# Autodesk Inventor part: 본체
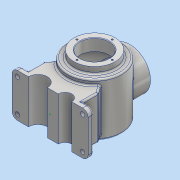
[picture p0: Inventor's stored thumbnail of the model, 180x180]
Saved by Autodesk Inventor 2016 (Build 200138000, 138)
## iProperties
Created: 2018-08
Part Number: 본체
Material: 알루미늄 6061
Document SubType Name: Modeling
Designer: 605-08
Density: 2.7 g/cm^3
Appearance: 알루미늄 - 평지
Mass: 1878.27 g
Surface Area: 1089.41 cm^2
Volume: 695.654 cm^3
Author: 605-08
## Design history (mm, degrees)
sketch "스케치1"
  geometry: 1 further point
sketch "스케치2"
  geometry: L1 (-70, 40)-(70, 40); L2 (70, 40)-(70, -40); L3 (70, -40)-(-70, -40); L4 (-70, -40)-(-70, 40); L5 (-70, 40)-(70, -40); L6 (70, 40)-(-70, -40); 1 further point
  constraints: 12 end point, 2 midpoint, 2 parallel, 1 horizontal, 1 perpendicular
  dimensions: "d0" = 140 distance of L2.end L3.end; "d1" = 80 distance of L1.end L2.end
extrude "돌출1" new body sketch "스케치2" distance "d2" = 10; taper "d3" = 0 deg
sketch "스케치5"
  geometry: L1 (-70, 0)-(-70, 10) reference; L2 (-50, 38.563)-(0, 109.97); L3 (-70, 10)-(70, 10) reference; L4 (-50, 10)-(50, 10); L5 (70, 0)-(-70, 0) reference; L6 (-50, 10)-(-50, 38.563); L7 (0, 10)-(0, 109.97); L8 (50, 10)-(50, 38.563); L9 (50, 38.563)-(0, 109.97); 3 further points
  constraints: 12 end point, 3 midpoint, 1 coincident, 1 horizontal, 1 perpendicular, 1 symmetric about line, 1 vertical, 1 vertical alignment
  dimensions: "d11" = 55 deg angle of L3 L2; "d12" = 100 distance of L4.start L4.end; "d13" = 99.97036 distance of point (0, 10) L2.end
extrude "돌출2" join sketch "스케치5" stored distance "d14" = 80; taper "d15" = 0 deg
sketch "스케치7"
  geometry: 1 further point
sketch "스케치8"
  geometry: C1 r 50 at (0, 82); 1 further point
  constraints: 1 centre point, 1 vertical alignment
  dimensions: "d24" = 100 diameter of C1; "d25" = 82 distance of C1.centre point (0, 0)
extrude "돌출3" join sketch "스케치8" distance "d26" = 50; taper "d28" = 0 deg; dims "d27" = 58, "d29" = 0
sketch "스케치9"
  geometry: L1 (32, -58)-(132, -58) reference; L2 (82, 58)-(82, -58); L3 (132, -58)-(132, 50) reference; L4 (32, -58)-(32, 50) reference; L5 (132, -46.671)-(132, -58); L6 (132, -58)-(82, -58); A1 r 116 centre (82, 58) between (82, -58) and (132, -46.671); 1 further point
  constraints: 6 end point, 2 collinear, 2 point on circle, 1 centre point, 1 midpoint, 1 point on line, 1 vertical, 1 vertical alignment
  dimensions: "d30" = 116 radius of A1
revolve "회전1" sketch "스케치9" stored, may be unused: angle "d34" = 90 deg
sketch "스케치10"
  geometry: C1 r 38 at (0, 0); 1 further point
  constraints: 1 centre point, 1 vertical alignment
  dimensions: "d35" = 76 diameter of C1; "d36" = 82 distance of point (0, -82) C1.centre
extrude "돌출4" join sketch "스케치10" distance "d37" = 12; taper "d38" = 0 deg
node "작업 평면1"
sketch "스케치11"
  geometry: L1 (50, 50)-(-50, 50) reference; C1 r 38 at (0, 0); 1 further point
  constraints: 1 centre point, 1 coincident
  dimensions: "d40" = 76 diameter of C1; "d41" = 50 distance from line of L1 C1.centre
extrude "돌출5" join sketch "스케치11" stored distance "d42" = 12; taper "d43" = 0 deg
sketch "스케치12"
  geometry: 2 further points
  constraints: 1 vertical alignment
  dimensions: "d44" = 82 distance of point (0, -82) point (0, 0)
hole "구멍1" sketch "스케치12" at (0, 0) diameter "d45" = 54; stored, may be unused: countersink angle "d49" = 90 deg, drill point angle "d51" = 0 deg; dims "d46" = 6, "d47" = 4, "d48" = 2, "d50" = 22
sketch "스케치13"
  geometry: L1 (109, 40)-(55, 40) reference; L2 (82, 40)-(122, 40); L3 (122, 40)-(122, -40.163); L4 (82, 40)-(82, -48); A1 r 116 centre (82, 58) between (32, -46.671) and (132, -46.671) reference; A2 r 106 centre (82, 58) between (82, -48) and (122, -40.163); 1 further point
  constraints: 6 end point, 2 point on circle, 1 centre point, 1 collinear, 1 midpoint, 1 perpendicular, 1 vertical
  dimensions: "d52" = 10 radial gap between concentric circles of A1 A2; "d53" = 40 distance of L2.start L2.end
revolve "회전2" sketch "스케치13" stored, may be unused: angle "d54" = 90 deg
sketch "스케치14"
  geometry: 2 further points
  constraints: 1 coincident
hole "구멍2" sketch "스케치14" at (0, 0) diameter "d55" = 54; stored, may be unused: countersink angle "d59" = 90 deg, drill point angle "d61" = 0 deg; dims "d56" = 6, "d57" = 4, "d58" = 2, "d60" = 50
sketch "스케치15"
  geometry: L1 (140, 0)-(0, 0) reference; C1 r 17.5 at (47.5, 0); C2 r 12.5 at (97.5, 0); 3 further points
  constraints: 2 centre point, 2 horizontal alignment, 2 midpoint
  dimensions: "d62" = 35 diameter of C1; "d63" = 25 diameter of C2; "d64" = 22.5 distance of C1.centre point (70, 0); "d65" = 27.5 distance of C2.centre point (70, 0)
extrude "돌출6" cut sketch "스케치15" stored distance "d66" = 12; taper "d67" = 0 deg
node "작업 평면2"
chamfer "모따기1" distance "d71" = 1; stored, may be unused: second distance "d72" = 2, angle "d73" = 45 deg
fillet "모깎기1" dims "d74" = 10
sketch "스케치17"
  geometry: A1 r 10 centre (-60, 30) between (-60, 40) and (-70, 30) reference; 2 further points
  constraints: 1 coincident
hole "구멍3" sketch "스케치17" at (-60, 30) diameter "d75" = 8; stored, may be unused: countersink angle "d79" = 90 deg, drill point angle "d81" = 0 deg; dims "d76" = 6, "d77" = 4, "d78" = 2, "d80" = 50
sketch "스케치18"
  geometry: A1 r 10 centre (-60, -30) between (-70, -30) and (-60, -40) reference; A2 r 10 centre (60, -30) between (60, -40) and (70, -30) reference; A3 r 10 centre (60, 30) between (70, 30) and (60, 40) reference; 4 further points
  constraints: 3 coincident
hole "구멍4" sketch "스케치18" at (-60, -30), (60, -30), (60, 30) diameter "d82" = 8; stored, may be unused: countersink angle "d86" = 90 deg, drill point angle "d88" = 0 deg; dims "d83" = 6, "d84" = 4, "d85" = 2, "d87" = 50
fillet "모깎기2" dims "d89" = 3
fillet "모깎기3" dims "d90" = 3
fillet "모깎기4" dims "d91" = 3
sketch "스케치19"
  geometry: C1 r 28 at (0, 0) reference; 2 further points
  constraints: 1 vertical alignment
  dimensions: "d92" = 32.5 distance of point (0, 32.5) C1.centre
hole "구멍5" sketch "스케치19" at (0, 32.5) diameter "d93" = 3.242; stored, may be unused: countersink angle "d97" = 90 deg, drill point angle "d99" = 118 deg; dims "d94" = 8, "d95" = 4, "d96" = 2, "d98" = 10
sketch "스케치20"
  geometry: 2 further points
  constraints: 1 vertical alignment
  dimensions: "d103" = 32.5 distance of point (0, 32.5) point (0, 0)
hole "구멍6" sketch "스케치20" at (0, 32.5) diameter "d104" = 3.242; stored, may be unused: countersink angle "d108" = 90 deg, drill point angle "d110" = 118 deg; dims "d105" = 8, "d106" = 4, "d107" = 2, "d109" = 10
fillet "모깎기5" dims "d114" = 3
fillet "모깎기6" dims "d115" = 3
node "작업 평면4"
sketch "스케치23"
  geometry: C1 r 32.5 at (0, 0); 1 further point
  constraints: 1 centre point, 1 vertical alignment, 1 other
  dimensions: "d119" = 65 diameter of C1; "d120" = 82 distance of point (0, -82) C1.centre
feature "엠보싱1" sketch "스케치23" dims "d121" = 0.5, "d122" = 0
fillet "모깎기7" dims "d123" = 3
node "솔리드1"
pattern_circular "원형 패턴1" dims angle "d101" = 360 deg
pattern_circular "원형 패턴2" dims angle "d112" = 360 deg
other parameters: "d39" = 147
